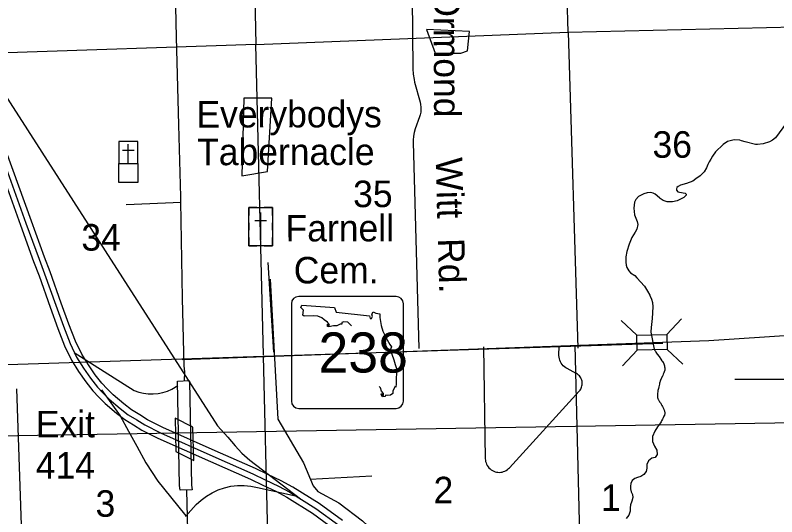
# Model space of a CAD drawing. Extents: x 2480962 to 2688785, y 277103 to 599240.
# Drawn here: x 2567838 to 2580754, y 367361 to 375869 of the extents above; entities that cross this region are included whole.
import ezdxf

# ---------------------------------------------------------------- set-up
doc = ezdxf.new("R2010")
doc.units = 0
for name, color, linetype in [('Bridges', 7, 'Continuous'), ('Culture', 7, 'Continuous'), ('Culture Text', 7, 'Continuous'), ('Divided_Highway', 7, 'Continuous'), ('Interstate Divided Highway Outline and Fill', 7, 'Continuous'), ('Interstate Highway Center Lines', 7, 'Continuous'), ('Interstate Ramps', 7, 'Continuous'), ('Level 31', 7, 'Continuous'), ('Local Roads Improved', 7, 'Continuous'), ('Local Roads Paved', 7, 'Continuous'), ('Local Roads Related Text', 7, 'Continuous'), ('Narrow River Creek and Branch and Slough', 7, 'Continuous'), ('Roadshields County Roads', 7, 'Continuous'), ('Roadshields State Highways', 7, 'Continuous'), ('Section Lines', 7, 'Continuous'), ('Section Numbers', 7, 'Continuous'), ('State Roads Related Text', 7, 'Continuous'), ('State Routes Highway Center Lines', 7, 'Continuous'), ('Township and Range lines', 7, 'Continuous'), ('US Route Divided Highway Outline and Fill', 7, 'Continuous'), ('US Routes Highway Center Lines', 7, 'Continuous')]:
    doc.layers.add(name, color=color, linetype=linetype)

msp = doc.modelspace()

# ---------------------------------------------------------------- linework, layer by layer
at = {"layer": 'Bridges'}
for p, q in [((2578890.138, 370455.772), (2579139.124, 370718.599)), ((2578378.326, 370441.931), (2578115.498, 370690.916)), ((2578897.059, 370199.866), (2579159.886, 369950.88)), ((2578385.246, 370186.024), (2578136.261, 369923.197)), ((2570548.282, 369032.914), (2570563.839, 368466.633)), ((2570852.557, 368881.432), (2570548.282, 369032.914)), ((2570868.114, 368315.151), (2570852.557, 368881.432)), ((2570563.839, 368466.633), (2570868.114, 368315.151))]:
    msp.add_line(p, q, dxfattribs=at)
msp.add_lwpolyline([(2578378.326, 370441.931), (2578890.138, 370455.772), (2578897.059, 370199.866), (2578385.246, 370186.024)], close=True, dxfattribs=at)
at = {"layer": 'Culture'}
for p, q in [((2569592.3, 373730.023), (2569592.3, 373355.023)), ((2569917.3, 373730.023), (2569592.3, 373730.023)), ((2569917.3, 373355.023), (2569917.3, 373730.023)), ((2569654.8, 373580.023), (2569854.943, 373580.023)), ((2569754.8, 373355.023), (2569754.8, 373680.171)), ((2569592.3, 373355.023), (2569917.3, 373355.023)), ((2571799.458, 372609.462), (2571799.458, 372471.962)), ((2571936.958, 372609.462), (2571799.458, 372609.462)), ((2571999.458, 372521.962), (2571999.458, 372059.462)), ((2572199.458, 372609.462), (2572061.958, 372609.462)), ((2572199.458, 372471.962), (2572199.458, 372609.462)), ((2571799.458, 372346.962), (2571799.458, 372221.962)), ((2571899.458, 372384.462), (2572099.458, 372384.462)), ((2572199.458, 372221.962), (2572199.458, 372346.962)), ((2571799.458, 372096.962), (2571799.458, 371959.462)), ((2572199.458, 371959.462), (2572199.458, 372096.962)), ((2571799.458, 371959.462), (2571936.958, 371959.462)), ((2572061.958, 371959.462), (2572199.458, 371959.462))]:
    msp.add_line(p, q, dxfattribs=at)
for points in [[(2569592.3, 373355.023), (2569917.3, 373355.023), (2569917.3, 373030.023), (2569592.3, 373030.023)], [(2571799.458, 372609.462), (2572199.458, 372609.462), (2572199.458, 371959.462), (2571799.458, 371959.462)]]:
    msp.add_lwpolyline(points, close=True, dxfattribs=at)
at = {"layer": 'Divided_Highway'}
msp.add_line((2562034.749, 368637.924), (2601597.398, 369311.486), dxfattribs=at)
at = {"layer": 'Interstate Divided Highway Outline and Fill'}
for points in [[(2573385.877, 367299.239), (2572991.132, 367585.43), (2572544.113, 367864.816), (2572350.53, 367971.621), (2572120.158, 368080.225), (2571911.264, 368178.144), (2571231.441, 368480.649), (2570343.408, 368876.05), (2570083.09, 369006.209), (2569950.344, 369088.386), (2569812.174, 369173.172), (2569681.683, 369275.7), (2569497.834, 369431.021), (2569398.029, 369530.826), (2569307.97, 369627.096), (2569195.421, 369770.909), (2569078.11, 369938.948), (2568965.516, 370117.222), (2568859.226, 370339.18), (2568747.355, 370626.849), (2568617.908, 370986.066), (2568429.182, 371516.449), (2568334.913, 371763.499), (2568114.327, 372376.599), (2567685.462, 373565.725)], [(2567497.425, 373497.59), (2567926.163, 372308.818), (2568147.372, 371693.987), (2568241.516, 371447.266), (2568429.616, 370918.64), (2568560.048, 370556.691), (2568675.571, 370259.631), (2568790.179, 370020.302), (2568911.477, 369828.248), (2569034.555, 369651.947), (2569155.897, 369496.898), (2569254.251, 369391.761), (2569362.35, 369283.663), (2569555.326, 369120.631), (2569697.708, 369008.759), (2569845.406, 368918.126), (2569985.533, 368831.381), (2570257.968, 368695.163), (2571150.111, 368297.932), (2571828.158, 367996.217), (2572035.072, 367899.226), (2572259.489, 367793.43), (2572442.731, 367692.331), (2572879.303, 367419.473), (2573264.196, 367140.426)]]:
    msp.add_lwpolyline(points, dxfattribs=at)
at = {"layer": 'Interstate Highway Center Lines'}
msp.add_lwpolyline([(2567591.444, 373531.657), (2568020.245, 372342.708), (2568241.143, 371728.743), (2568335.349, 371481.857), (2568523.762, 370952.353), (2568653.701, 370591.77), (2568767.399, 370299.405), (2568877.848, 370068.762), (2568994.793, 369883.598), (2569114.988, 369711.428), (2569231.933, 369561.997), (2569326.14, 369461.294), (2569430.092, 369357.342), (2569618.504, 369198.166), (2569754.941, 369090.965), (2569897.875, 369003.256), (2570034.312, 368918.795), (2570300.688, 368785.607), (2571190.776, 368389.29), (2571869.711, 368087.18), (2572077.615, 367989.726), (2572305.009, 367882.525), (2572493.422, 367778.573), (2572935.217, 367502.451), (2573325.037, 367219.832)], dxfattribs=at)
at = {"layer": 'Interstate Ramps'}
msp.add_line((2568838.797, 370150.31), (2569854.419, 369501.807), dxfattribs=at)
for points in [[(2566674.295, 376054.664), (2571268.861, 368903.823), (2571442.573, 368713.49), (2571568.879, 368565.459), (2571679.405, 368438.574), (2571816.38, 368322.232), (2572676.69, 367664.031)], [(2569854.419, 369501.807), (2569932.485, 369474.991), (2570012.928, 369456.482), (2570094.864, 369446.484), (2570177.397, 369445.104), (2570259.622, 369452.36), (2570340.638, 369468.17), (2570419.557, 369492.363), (2570495.517, 369524.673), (2570593.979, 369589.835)], [(2569298.419, 369512.762), (2569618.942, 369072.99), (2569760.73, 368814.008), (2569902.537, 368560.307), (2570054.807, 368274.9), (2570254.536, 367963.038), (2570470.27, 367698.707), (2570732.494, 367374.329)], [(2570726.87, 367363.074), (2570905.699, 367568.044), (2570988.873, 367644.696), (2571079.603, 367712.234), (2571176.896, 367769.918), (2571279.685, 367817.115), (2571386.846, 367853.31), (2571497.201, 367878.105), (2571609.544, 367891.229), (2571722.643, 367892.537), (2571835.259, 367882.016), (2571946.158, 367859.781), (2572592.258, 367716.801)]]:
    msp.add_lwpolyline(points, dxfattribs=at)
at = {"layer": 'Level 31'}
for points in [[(2574813.474, 375627.946), (2574959.284, 375226.7), (2575396.714, 375226.7), (2575506.072, 375263.177), (2575542.524, 375591.469)], [(2571678.555, 373147.514), (2572115.985, 373220.467), (2572188.891, 374460.684), (2571715.007, 374460.684)]]:
    msp.add_lwpolyline(points, close=True, dxfattribs=at)
at = {"layer": 'Local Roads Improved'}
for p, q in [((2574563.753, 377068.854), (2574580.727, 374961.805)), ((2574612.605, 374732.35), (2574705.034, 374395.806)), ((2574695.868, 374146.25), (2574623.742, 373943.295)), ((2574587.726, 373715.549), (2574684.982, 370214.94)), ((2570652.905, 372690.143), (2569716.616, 372652.393)), ((2575782.184, 370242.79), (2575810.631, 368346.22)), ((2577059.608, 370109.039), (2577061.121, 370252.128)), ((2577351.33, 369794.211), (2577198.886, 369874.916)), ((2576219.611, 368191.268), (2577404.197, 369490.373))]:
    msp.add_line(p, q, dxfattribs=at)
for points in [[(2574580.727, 374961.805), (2574586.374, 374868.443), (2574601.749, 374776.183), (2574612.605, 374732.35)], [(2574705.034, 374395.806), (2574714.356, 374353.257), (2574719.178, 374309.968), (2574719.451, 374266.412), (2574715.167, 374223.066), (2574706.378, 374180.404), (2574695.868, 374146.25)], [(2574623.742, 373943.295), (2574605.002, 373880.287), (2574592.949, 373815.664), (2574587.718, 373750.136), (2574587.726, 373715.549)], [(2577198.886, 369874.916), (2577175.374, 369888.986), (2577153.461, 369905.437), (2577133.388, 369924.088), (2577115.375, 369944.735), (2577099.618, 369967.153), (2577086.291, 369991.094), (2577075.54, 370016.298), (2577067.482, 370042.487), (2577062.205, 370069.375), (2577059.769, 370096.667), (2577059.608, 370109.039)], [(2577404.197, 369490.373), (2577417.146, 369506.161), (2577428.374, 369523.214), (2577437.759, 369541.349), (2577445.196, 369560.365), (2577450.605, 369580.054), (2577453.925, 369600.201), (2577455.123, 369620.584), (2577454.183, 369640.98), (2577451.116, 369661.168), (2577445.955, 369680.923), (2577438.758, 369700.031), (2577429.604, 369718.282), (2577418.591, 369735.475), (2577405.841, 369751.424), (2577391.495, 369765.952), (2577375.708, 369778.902), (2577358.654, 369790.129), (2577351.33, 369794.211)], [(2567857.252, 369530.73), (2567937.438, 367221.38)], [(2575810.631, 368346.22), (2575812.288, 368321.656), (2575816.504, 368297.399), (2575823.232, 368273.717), (2575832.399, 368250.867), (2575843.903, 368229.101), (2575857.621, 368208.656), (2575873.399, 368189.757), (2575891.068, 368172.612), (2575910.431, 368157.406), (2575931.277, 368144.309), (2575953.379, 368133.462), (2575976.494, 368124.986), (2576000.367, 368118.971), (2576024.739, 368115.485), (2576049.341, 368114.567), (2576073.905, 368116.224), (2576098.161, 368120.44), (2576121.844, 368127.168), (2576144.693, 368136.336), (2576166.458, 368147.841), (2576186.903, 368161.559), (2576205.802, 368177.339), (2576219.611, 368191.268)]]:
    msp.add_lwpolyline(points, dxfattribs=at)
at = {"layer": 'Local Roads Paved'}
for p, q in [((2572226.49, 370154.31), (2572128.251, 371672.867)), ((2572840.79, 368000.629), (2573884.212, 368054.253))]:
    msp.add_line(p, q, dxfattribs=at)
msp.add_lwpolyline([(2572162.987, 371389.644), (2572292.092, 369017.334), (2572727.823, 368274.978), (2572889.204, 367887.662), (2572969.895, 367790.833), (2573324.935, 367597.175), (2573728.389, 367290.55), (2574164.119, 366887.096), (2574648.264, 366370.674), (2575148.548, 365660.595), (2575439.035, 365111.897)], dxfattribs=at)
at = {"layer": 'Narrow River Creek and Branch and Slough'}
for points in [[(2581024.75, 374191.41), (2580734.5, 373790.34), (2580682, 373749.22), (2580629.25, 373719.19), (2580521.25, 373685.44), (2580427.25, 373674.81), (2580393.5, 373676.31), (2580216.25, 373719.81), (2580158, 373736.84), (2580126.5, 373750.19), (2580029.75, 373756.19), (2579919.25, 373726.53), (2579845.25, 373677.41), (2579714.5, 373553.09), (2579662.5, 373475.91), (2579634.5, 373427.56), (2579606.25, 373381.31), (2579582.75, 373338.59), (2579559.75, 373278.53), (2579522.25, 373209.91), (2579455.75, 373144.97), (2579379.25, 373091.66), (2579329.25, 373056.09), (2579226, 373016.91), (2579122.75, 372986.69), (2579084.25, 372966.62), (2579060.5, 372946.09), (2579051.25, 372925.12), (2579054, 372901.59), (2579073.75, 372874.19), (2579103, 372864.97), (2579202.25, 372852.06), (2579219.5, 372832.94), (2579217.25, 372816.25), (2579177, 372777.41), (2579064.25, 372720), (2578985, 372702.72), (2578895.5, 372704.66), (2578827.5, 372725.72), (2578778.75, 372758.88), (2578766.5, 372769.06), (2578693, 372833.72), (2578658.75, 372849.12), (2578620, 372860.25), (2578557.25, 372857.09), (2578499.5, 372842.25), (2578408.75, 372792.16), (2578363.5, 372745.59), (2578342.5, 372697.38), (2578329.75, 372595.88), (2578339, 372483.66), (2578386.75, 372370), (2578399.75, 372318.88), (2578379.25, 372238.75), (2578353.75, 372187.69), (2578297.25, 372098.62), (2578253.25, 371986.19), (2578209.5, 371863.34), (2578194, 371772.91), (2578193.25, 371680.62), (2578201.25, 371627.34), (2578214, 371587.31), (2578244, 371533.72), (2578276, 371500.25), (2578344.25, 371451.47), (2578383.5, 371416.06), (2578509.25, 371273.91), (2578563.75, 371188.78), (2578598.75, 371121.41), (2578608.75, 371104.22), (2578631.25, 371053.97), (2578646.75, 370994.56), (2578652.75, 370922.53), (2578641.75, 370726.69), (2578622.5, 370570.28), (2578619.272, 370499.711)], [(2578619.272, 370499.711), (2578620.353, 370494.831), (2578676.46, 370203.687), (2578681.932, 370192.95), (2578686.907, 370183.669), (2578696.017, 370167.676), (2578703.172, 370155.882), (2578714.397, 370138.498), (2578726.18, 370121.466), (2578756.979, 370078.895), (2578787.833, 370036.39), (2578807.516, 370008.891), (2578817.253, 369995.029), (2578826.911, 369980.972), (2578829.817, 369976.427), (2578832.313, 369972.051), (2578834.465, 369967.855), (2578838.049, 369959.774), (2578840.751, 369952.504), (2578842.824, 369946.019), (2578845.897, 369934.458), (2578847.829, 369925.67), (2578850.305, 369912.42), (2578852.498, 369899.238), (2578853.648, 369891.765), (2578854.514, 369885.142), (2578855.112, 369879.305), (2578855.677, 369869.06), (2578855.584, 369861.406), (2578855.161, 369855.712), (2578854.62, 369851.48), (2578853.408, 369845.213), (2578851.666, 369839.069), (2578844.288, 369818.056), (2578838.383, 369802.474), (2578829.043, 369779.299), (2578819.271, 369756.259), (2578814.279, 369745.097), (2578795.771, 369706.587), (2578791.243, 369696.921), (2578784.804, 369682.255), (2578781.807, 369674.816), (2578778.996, 369667.287), (2578774.84, 369654.932), (2578771.556, 369644.042), (2578766.422, 369624.838), (2578762.93, 369610.336), (2578752.949, 369566.549), (2578746.673, 369538.913), (2578742.307, 369518.165), (2578739.233, 369502.595), (2578734.957, 369479.231), (2578731.097, 369455.863), (2578730.176, 369449.282), (2578729.505, 369443.082), (2578728.764, 369431.394), (2578728.692, 369421.122), (2578729.088, 369412.117), (2578729.799, 369404.236), (2578730.708, 369397.348), (2578731.73, 369391.331), (2578734.038, 369380.838), (2578736.215, 369373.011), (2578738.106, 369367.171), (2578741.368, 369358.471), (2578745.154, 369349.853), (2578747.886, 369344.315), (2578753.343, 369334.374), (2578758.403, 369326.062), (2578767.655, 369312.115), (2578781.695, 369291.723), (2578788.411, 369281.339), (2578791.618, 369276.014), (2578794.695, 369270.567), (2578806.022, 369249.587), (2578814.346, 369233.814), (2578826.537, 369209.836), (2578832.494, 369197.606), (2578838.354, 369185.157), (2578841.494, 369178.092), (2578844.05, 369171.856), (2578848.04, 369160.839), (2578850.583, 369152.509), (2578852.21, 369146.233), (2578854.161, 369136.788), (2578855.477, 369127.327), (2578855.807, 369122.086), (2578855.765, 369117.449), (2578855.491, 369113.368), (2578854.51, 369106.204), (2578853.387, 369100.843), (2578851.14, 369092.88), (2578848.296, 369085.087), (2578841.123, 369067.89), (2578835.581, 369055.295), (2578826.888, 369036.727), (2578817.59, 369018.348), (2578800.655, 368986.683), (2578791.901, 368971.043), (2578782.807, 368955.545)], [(2578782.807, 368955.545), (2578732.226, 368885.385), (2578688.227, 368811.057), (2578649.096, 368724.524), (2578646.008, 368638.337), (2578682.927, 368556.538), (2578717.693, 368488.746), (2578726.492, 368414.693), (2578692.942, 368368.288), (2578636.981, 368357.734), (2578577.399, 368311.079), (2578550.048, 368246.7), (2578550.709, 368184.592), (2578537.289, 368128.361), (2578499.755, 368079.913), (2578446.075, 368043.334), (2578390.156, 368028.773), (2578344.272, 368012.306), (2578300.623, 367973.817), (2578277.128, 367923.501), (2578271.569, 367881.371), (2578276.043, 367837.332), (2578286.652, 367781.33), (2578305.101, 367741.433), (2578311.663, 367689.399), (2578298.307, 367627.158), (2578272.98, 367560.794), (2578267.506, 367510.65), (2578266.101, 367454.532), (2578242.754, 367390.192), (2578201.322, 367331.688)]]:
    msp.add_lwpolyline(points, dxfattribs=at)
at = {"layer": 'Roadshields State Highways'}
for p, q in [((2572521.513, 370973.145), (2572521.513, 369323.145)), ((2574296.513, 371098.145), (2572646.513, 371098.145)), ((2574421.513, 369323.145), (2574421.513, 370973.145)), ((2572646.513, 369198.145), (2574296.513, 369198.145))]:
    msp.add_line(p, q, dxfattribs=at)
for points in [[(2573541.152, 370599.046), (2573521.45, 370624.39), (2573478.596, 370660.671), (2573409.37, 370670.566), (2573379.702, 370657.373), (2573376.406, 370627.688), (2573346.738, 370630.987), (2573293.994, 370601.302), (2573234.658, 370601.302), (2573158.839, 370581.513), (2573132.468, 370588.109), (2573135.764, 370630.987), (2573152.247, 370601.302), (2573168.729, 370617.794), (2573132.468, 370660.671), (2573076.428, 370703.549), (2573040.167, 370733.233), (2572967.645, 370766.216), (2572891.826, 370769.514), (2572736.892, 370766.216), (2572713.817, 370782.708), (2572727.003, 370868.463), (2572680.853, 370911.34), (2572697.335, 370950.92)], [(2572697.335, 370950.92), (2573251.14, 370911.34), (2573280.808, 370832.182), (2573844.503, 370769.514), (2573857.689, 370723.339), (2573880.764, 370723.339), (2573897.247, 370756.321), (2573887.357, 370795.901), (2573907.136, 370835.48), (2573956.583, 370812.392), (2574022.512, 370802.497), (2574022.512, 370739.83), (2574042.291, 370604.6), (2574075.256, 370508.95), (2574144.481, 370360.528), (2574190.632, 370281.369), (2574217.003, 370245.088), (2574197.225, 370189.017), (2574223.596, 370119.754), (2574256.561, 370024.104), (2574279.636, 369944.945), (2574306.008, 369875.681), (2574306.008, 369813.014), (2574299.415, 369687.679), (2574296.118, 369615.117), (2574292.822, 369559.046), (2574279.636, 369575.538), (2574263.154, 369539.257), (2574240.079, 369499.677), (2574240.079, 369453.501), (2574200.521, 369423.817), (2574157.667, 369417.22), (2574121.406, 369423.817), (2574108.22, 369404.027), (2574065.366, 369397.431), (2574045.587, 369433.712), (2574055.477, 369450.203), (2574068.663, 369427.115), (2574085.145, 369420.519), (2574085.145, 369450.203), (2574048.884, 369493.081), (2574035.698, 369545.853), (2574013.202, 369570.408)]]:
    msp.add_lwpolyline(points, dxfattribs=at)
for centre, start, end in [((2572646.513, 370973.145), 90, 180), ((2574296.513, 370973.145), 0, 90), ((2572646.513, 369323.145), 180, 270), ((2574296.513, 369323.145), 270, 0)]:
    msp.add_arc(centre, 125, start, end, dxfattribs=at)
at = {"layer": 'Section Lines'}
for p, q in [((2577215.749, 375583.412), (2577090.732, 380917.794)), ((2571832.847, 380707.507), (2571916.34, 375374.024)), ((2577215.749, 375583.412), (2582500.867, 375708.31)), ((2571916.34, 375374.024), (2577215.749, 375583.412)), ((2577215.749, 375583.412), (2577381.164, 370218.528)), ((2571916.34, 375374.024), (2566704.147, 375198.504)), ((2572049.907, 370105.122), (2571916.34, 375374.024)), ((2577467.544, 364916.291), (2577337.353, 370272.567)), ((2572312.257, 359442.977), (2572050.421, 370086.358))]:
    msp.add_line(p, q, dxfattribs=at)
at = {"layer": 'State Roads Related Text'}
msp.add_line((2580044.761, 369696.941), (2581856.381, 369695.363), dxfattribs=at)
at = {"layer": 'State Routes Highway Center Lines'}
for p, q in [((2579601.565, 370349.403), (2581317.266, 370466.338)), ((2570670.632, 370030.487), (2579601.565, 370349.403))]:
    msp.add_line(p, q, dxfattribs=at)
at = {"layer": 'Township and Range lines'}
msp.add_line((2578822.988, 370300.509), (2566731.831, 369906.656), dxfattribs=at)
at = {"layer": 'US Route Divided Highway Outline and Fill'}
for p, q in [((2570589.382, 369663.91), (2570789.526, 369671.209)), ((2570789.526, 369671.209), (2570792.196, 369653.76)), ((2570837.756, 367818.373), (2570637.846, 367812.369))]:
    msp.add_line(p, q, dxfattribs=at)
for points in [[(2570637.846, 367812.369), (2570625.302, 367893.179), (2570589.382, 369663.91)], [(2570792.196, 369653.76), (2570825.244, 367898.097), (2570837.756, 367818.373)]]:
    msp.add_lwpolyline(points, dxfattribs=at)
at = {"layer": 'US Routes Highway Center Lines'}
for points in [[(2570554.864, 376010.704), (2570565.508, 375494.491), (2570608.082, 374009.712), (2570640.013, 372791.023), (2570640.013, 372711.196), (2570671.944, 371066.763), (2570698.553, 369922.579), (2570709.196, 369821.465), (2570703.499, 369668.259)], [(2570741.622, 367805.154), (2570822.843, 364647.345), (2570828.42, 364261.766), (2570812.813, 363939.538), (2570809.718, 363355.715), (2570617.971, 362403.369), (2569355.341, 355940.301), (2568545.189, 351306.714), (2567725.875, 346111.943), (2567681.24, 345829.256), (2567603.129, 345349.434), (2567510.14, 344676.194), (2567472.945, 344144.298), (2567399.21, 343614.317), (2567405.524, 342256.847), (2567426.292, 336953.603), (2567575.5, 331404.13), (2567801.75, 325711.575), (2568118.15, 315272.099), (2568140.009, 314316.086), (2568150.797, 314025.592), (2568166.804, 313819.618), (2568198.641, 313640.078), (2568373.481, 313006.506)]]:
    msp.add_lwpolyline(points, dxfattribs=at)

# ---------------------------------------------------------------- texts
at = {"layer": 'Culture Text'}
for s, rotation, p in [('Everybodys', 0.0672472, (2570911.524, 373963.939)), ('Tabernacle', 0.0672528, (2570922.47, 373324.849)), ('Farnell', 0.0672667, (2572423.428, 372031.643)), ('Cem.', 0.0672722, (2572561.853, 371319.124))]:
    msp.add_text(s, height=450, rotation=rotation, dxfattribs=at).set_placement(p)
at = {"layer": 'Local Roads Related Text'}
for s, rotation, p in [('SE Ormond', 270.2748333, (2574927.947, 377277.488)), ('Witt  Rd.', 271.5488583, (2574968.268, 373451.824))]:
    msp.add_text(s, height=450, rotation=rotation, dxfattribs=at).set_placement(p)
at = {"layer": 'Roadshields County Roads'}
for s, p in [('Exit', (2568186.076, 368708.08)), ('414', (2568186.088, 368008.08))]:
    msp.add_text(s, height=450, rotation=0.0009944, dxfattribs=at).set_placement(p)
at = {"layer": 'Roadshields State Highways'}
msp.add_text('238', height=680, dxfattribs=at).set_placement((2572981.132, 369808.146))
at = {"layer": 'Section Numbers'}
for s, rotation, p in [('36', 0.0672528, (2578646.635, 373451.278)), ('35', 0.0672583, (2573568.922, 372613.403)), ('34', 0.0672639, (2568959.953, 371875.723)), ('2', 0.0672806, (2574932.749, 367589.142)), ('1', 0.0672806, (2577771.16, 367460.822)), ('3', 0.0672778, (2569199.651, 367360.665))]:
    msp.add_text(s, height=450, rotation=rotation, dxfattribs=at).set_placement(p)

doc.saveas('drawing.dxf')
